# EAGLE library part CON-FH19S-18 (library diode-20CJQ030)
Hirose FH19 & FH19S Series 0.5mm pitch, 0.9mm above the board, Flexible Printed Circuit & Flexible Flat Cable Connectors Features: 1. Low-profile 0.5mm pitch FPC, FFC Connectors Miniaturization of portable equipment and personal mobile devices has created increased demand for a low profile, high density, and high reliability connectors. *The design of this connector has been made thinner and smaller, with a height of 0.9mm and width of 3mm. [As of August 2002, this is the smallest connector of this type available on the market !] *PCB footprint: Reduced approximately 48% (as compared with Hirose Electric's 0.5mm pitch FH12 Series connectors) *Connector weight: Reduced approximately 78% (as compared with Hirose Electric's 0.5mm pitch FH12 Series connectors) 2. Conductive traces on the PCB can be designed to run under the connector All bottom surface of the connector is solid, without any exposure of the contact. 3. Proven Flip-Lock Actuator System assures easy and reliable operation Rotating actuator permits easy insertion and reliable connection with the FPC & FFC. Tactile sensation confirms complete mechanical locking of the actuator and the electrical connection. 4. Accepts 0.2mm & 0.3mm thick FPC, FFC Accepts 0.2mm & 0.3mm thick FPC, FFC, easy inserted in the connector. The connector will also terminate successfully with 0.2mm thick Flat Flexible Cable (FFC). 5. Designed for placement with automatic equipment Packaged in embossed tape, on reel. One reel contains 5,000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
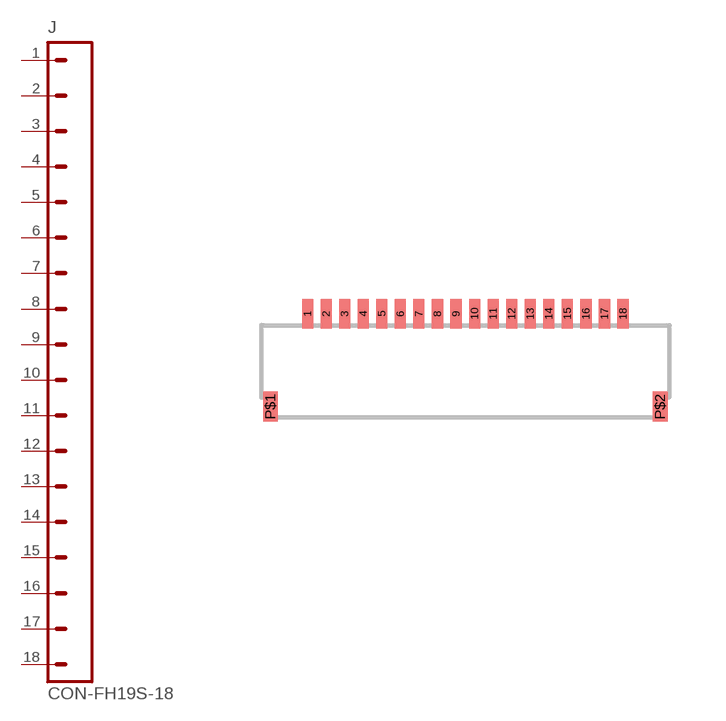
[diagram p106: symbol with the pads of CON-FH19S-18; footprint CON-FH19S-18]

Designator prefix J

## CON-FH19S-18  [CON-FH19S-18]
1  1  pas
2  2  pas
3  3  pas
4  4  pas
5  5  pas
6  6  pas
7  7  pas
8  8  pas
9  9  pas
10  10  pas
11  11  pas
12  12  pas
13  13  pas
14  14  pas
15  15  pas
16  16  pas
17  17  pas
18  18  pas

## Footprint CON-FH19S-18 (pad centres in mm)
Hirose FH19S 18pin 0.5mm pitch FPC/FFC connector
smd 0.3 x 0.8: 1 -4.25,2.5; 2 -3.75,2.5; 3 -3.25,2.5; 4 -2.75,2.5; 5 -2.25,2.5; 6 -1.75,2.5; 7 -1.25,2.5; 8 -0.75,2.5; 9 -0.25,2.5; 10 0.25,2.5; 11 0.75,2.5; 12 1.25,2.5; 13 1.75,2.5; 14 2.25,2.5; 15 2.75,2.5; 16 3.25,2.5; 17 3.75,2.5; 18 4.25,2.5
smd 0.4 x 0.8: P$1 -5.25,0; P$2 5.25,0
